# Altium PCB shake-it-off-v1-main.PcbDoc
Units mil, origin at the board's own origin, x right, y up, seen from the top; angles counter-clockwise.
Board outline 3355 x 2200 mil, 2 copper layers (Top Layer, Bottom Layer); 28 components, 43 nets, 116 pads, 6 vias.
Unrouted connection lines stored in the file: 1.
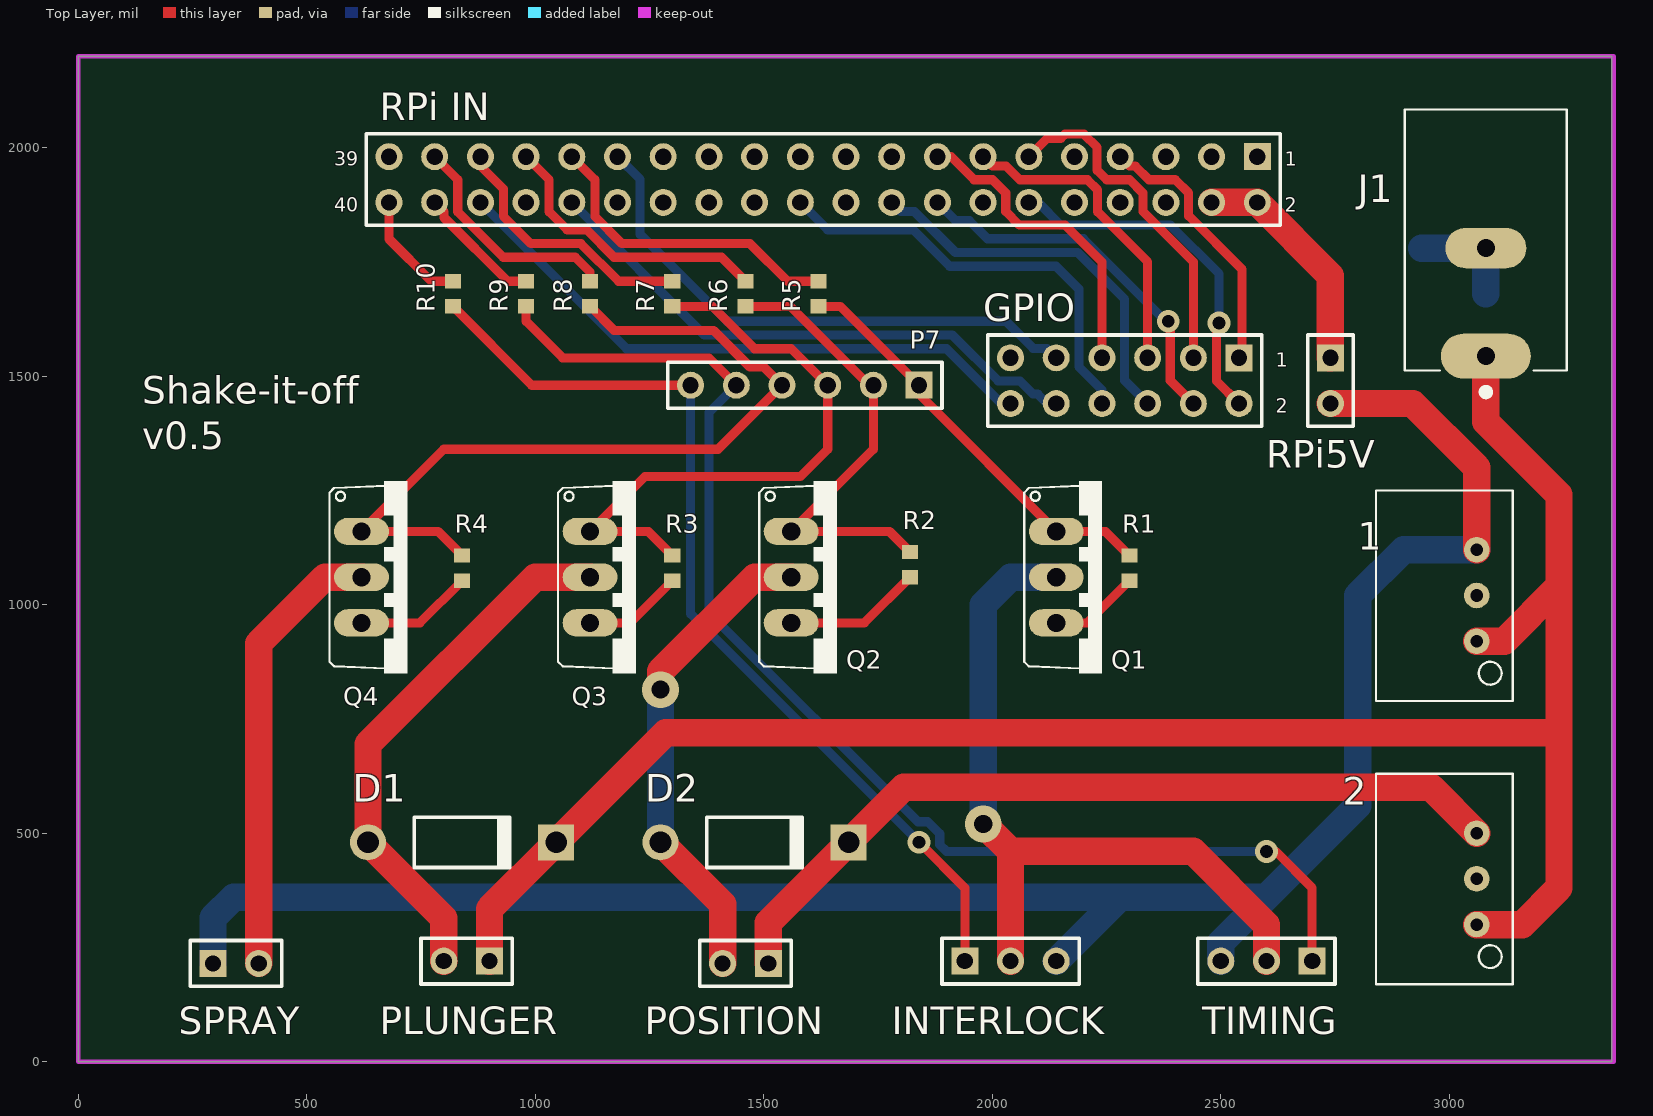
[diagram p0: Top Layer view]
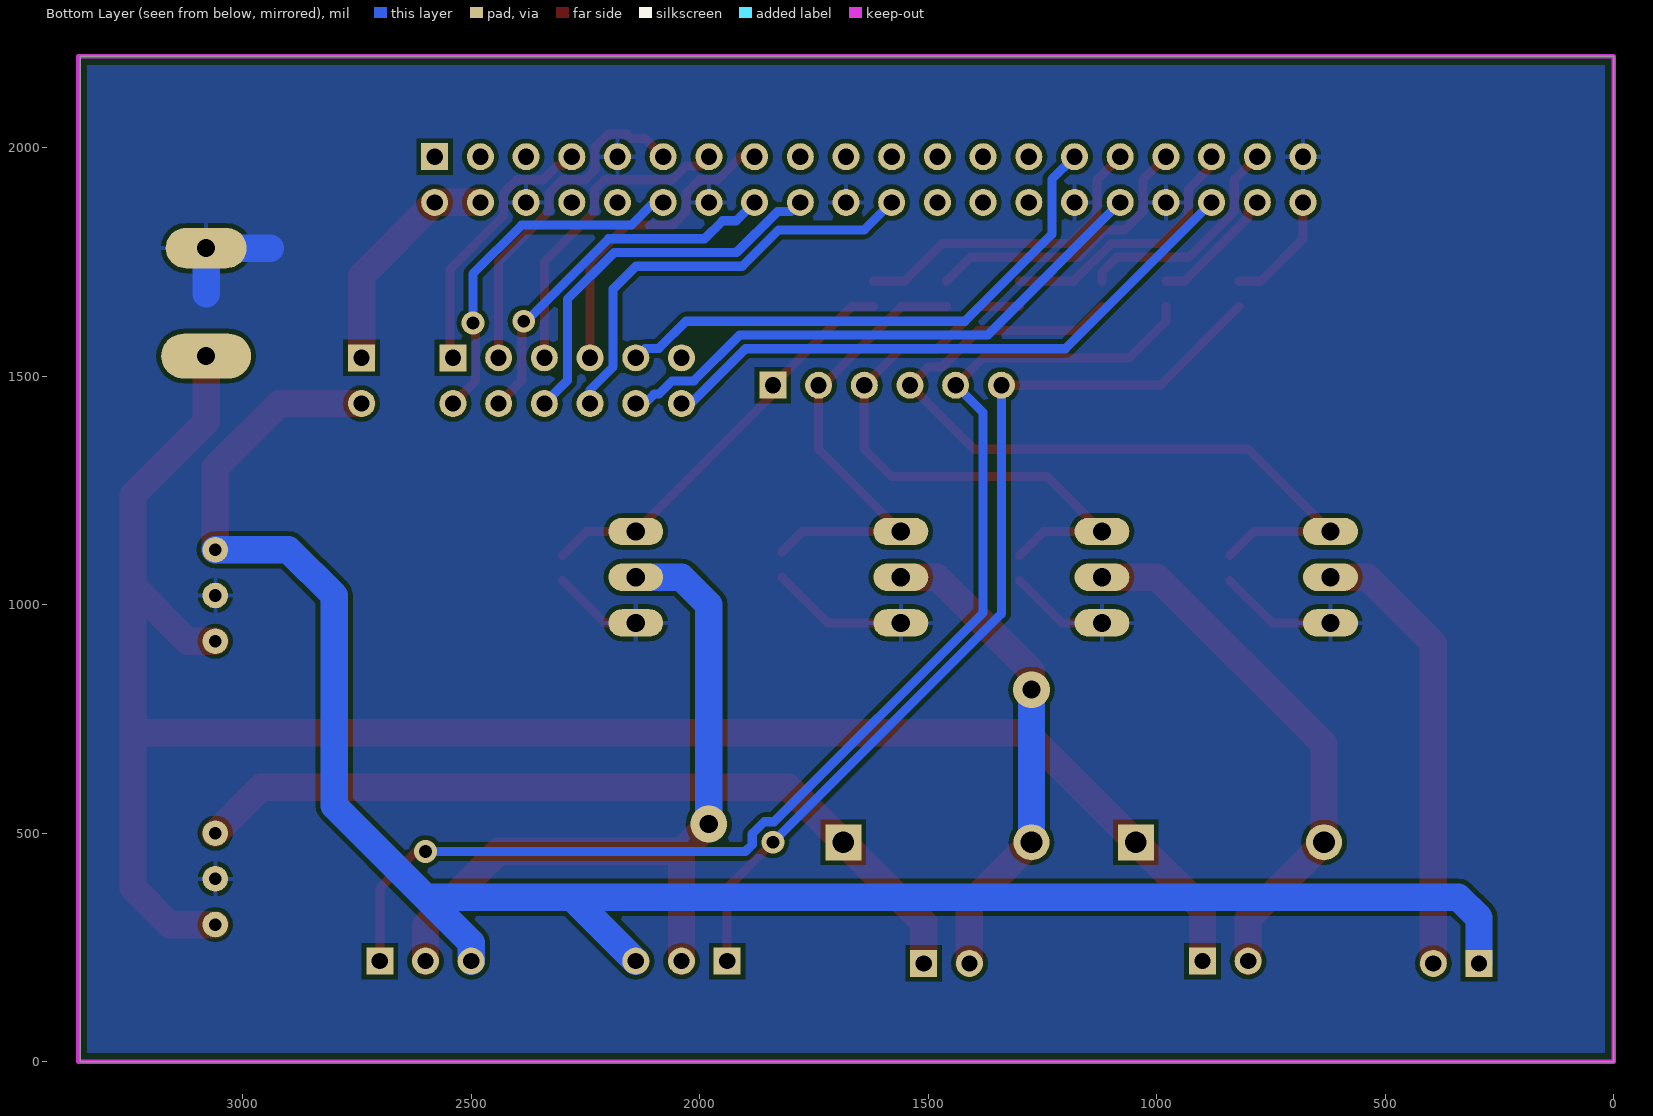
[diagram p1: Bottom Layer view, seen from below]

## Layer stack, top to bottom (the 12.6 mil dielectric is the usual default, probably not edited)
Top Solder: solder mask 0.4, Solder Resist, Dk 3.5
Top Layer: signal copper 1.4
Dielectric 1: dielectric 12.6, FR-4, Dk 4.8
Bottom Layer: signal copper 1.4
Bottom Solder: solder mask 0.4, Solder Resist, Dk 3.5

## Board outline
0,0 3355,0 3355,2200 0,2200

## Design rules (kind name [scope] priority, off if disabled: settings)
Clearance [All] p1: gap=10 ignorepadtopadclearanceinfootprint=FALSE except(0: Arc-Hole Track-Hole SMDPad-Hole THPad-Hole Via-Hole Fill-Hole Poly-Hole Region-Hole Text-Hole)
PolygonConnect [All] p1: connectstyle=Relief reliefconductorwidth=10 reliefentries=4 polygonreliefangle="90 Angle" airgapwidth=10
RoutingVias [All] p1: holewidth=35 width=60 viastyle="Through Hole" minholewidth=28 minwidth=50 maxholewidth=40 maxwidth=80
SolderMaskExpansion [All] p1: expansion=4
Width [All] p1: maxlimit=60 minlimit=20 preferedwidth=25 minimp=50.000000 maximp=50.000000 favimp=50.000000
30 further rules are at their usual default settings.

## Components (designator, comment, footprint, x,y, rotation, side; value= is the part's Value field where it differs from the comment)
1 "TSR1-2450" *TSR1-2450 3139.53,799.92 r90 top
2 "TSR1-24120" *TSR1-2450 3139.53,179.92 r90 top
D1 "Diode 1N4001" DO-41 840,480 r0 top
D2 "Diode 1N4001" DO-41 1480,480 r0 top
GPIO "Header 6X2" HDR2X6 2540,1540 r180 top (schematic designator P8)
INTERLOCK "Obstruction Sensor" HDR1X3 1940,220 r0 top (schematic designator P5)
J1 "PJ-037AH" *CUI_PJ-037AH 3080,1543.78 r90 top
P7 "Header 6" HDR1X6 1840,1480 r180 top
PLUNGER "Plunger Solenoid" HDR1X2 1510,215 r180 top (schematic designator P2)
POSITION "Piezo Solenoid" HDR1X2 900,220 r180 top (schematic designator P1)
Q1 "FQP30N06L" *TO220V 2240,1060 r270 top
Q2 "FQP30N06L" *TO220V 1660,1060 r270 top
Q3 "FQP30N06L" *TO220V 1220,1060 r270 top
Q4 "FQP30N06L" *TO220V 720,1060 r270 top
R1 "Res1" 1608[0603] 2300,1080 r90 top value=10K
R2 "Res1" 1608[0603] 1820,1087.56 r90 top value=10K
R3 "Res1" 1608[0603] 1300,1080 r90 top value=10K
R4 "Res1" 1608[0603] 840,1080 r90 top value=10K
R5 "Res1" 1608[0603] 1620,1680 r270 top value=0
R6 "Res1" 1608[0603] 1460,1680 r270 top value=0
R7 "Res1" 1608[0603] 1300,1680 r270 top value=0
R8 "Res1" 1608[0603] 1120,1680 r270 top value=0
R9 "Res1" 1608[0603] 980,1680 r270 top value=0
R10 "Res1" 1608[0603] 820,1680 r270 top value=0
RPi5V "Jumper - Remove if Powering RPi with its supply" HDR1X2 2740,1540 r270 top (schematic designator W1)
"RPi IN" "RPi GPIO In" HDR2X20 2580,1980 r180 top (schematic designator P6)
SPRAY "Sprayer" HDR1X2 295,215 r0 top (schematic designator P3)
TIMING "Safety Interlock" HDR1X3 2700,220 r180 top (schematic designator P4)

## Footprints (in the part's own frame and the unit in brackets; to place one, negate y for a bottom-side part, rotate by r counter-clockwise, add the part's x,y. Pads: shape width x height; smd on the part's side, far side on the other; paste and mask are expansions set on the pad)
1608[0603] [mm] "Chip Capacitor, Body 1.6x0.8mm, IPC High Density"
  rect 0.8x0.9 smd: 1(-0.7,0) 2(0.7,0)
  body extent -0.87,-0.48 0.87,0.48, height 1.3
*CUI_PJ-037AH [mm]
  oval 2.5x5 hole 1: 1(0,0)
  oval 2.25x4.5 hole 1: 2(6,0)
  silkscreen extent -2.2,-4.5 13.7,4.5
*TO220V [mil]
  oval 60x120 hole 40: 1(-100,-100) 2(0,-100) 3(100,-100)
  silkscreen extent -210,-170 210,0
*TSR1-2450 [mm]
  round 1.422 hole 0.7: 1(3.05,2.02) 2(5.59,2.02) 3(8.13,2.02)
  silkscreen extent -0.27,0.02 11.43,7.62
DO-41 [mm] "Diode, Axial; Body 5.2 x 2.7 mm (LxDia. max), Lead Dia. 0.86 mm (max)"
  round 2 hole 1.2: 1(-5.23,0)
  rect 2x2 hole 1.2: 2(5.23,0)
  silkscreen extent -2.65,-1.4 2.75,1.4
HDR1X2 [mm] "Connector; Header; 2 Position"
  rect 1.5x1.5 hole 0.9: 1(0,0)
  round 1.5 hole 0.9: 2(2.54,0)
  silkscreen extent -1.27,-1.27 3.81,1.27
HDR1X3 [mm] "Connector; Header; 3 Position"
  rect 1.5x1.5 hole 0.9: 1(0,0)
  round 1.5 hole 0.9: 2(2.54,0) 3(5.08,0)
  silkscreen extent -1.27,-1.27 6.35,1.27
HDR1X6 [mm] "Connector; Header; 6 Position"
  rect 1.5x1.5 hole 0.9: 1(0,0)
  round 1.5 hole 0.9: 2(2.54,0) 3(5.08,0) 4(7.62,0) 5(10.16,0) 6(12.7,0)
  silkscreen extent -1.27,-1.27 13.97,1.27
HDR2X6 [mm] "Connector; Header; 6x2 Position"
  rect 1.5x1.5 hole 0.9: 1(0,0)
  round 1.5 hole 0.9: 2(0,2.54) 3(2.54,0) 4(2.54,2.54) 5(5.08,0) 6(5.08,2.54) 7(7.62,0) 8(7.62,2.54) 9(10.16,0) 10(10.16,2.54) 11(12.7,0) 12(12.7,2.54)
  silkscreen extent -1.27,-1.27 13.97,3.81
HDR2X20 [mm] "Connector; Header; 20x2 Position"
  rect 1.5x1.5 hole 0.9: 1(0,0)
  round 1.5 hole 0.9: 2(0,2.54) 3(2.54,0) 4(2.54,2.54) 5(5.08,0) 6(5.08,2.54) 7(7.62,0) 8(7.62,2.54) 9(10.16,0) 10(10.16,2.54) 11(12.7,0) 12(12.7,2.54) 13(15.24,0) 14(15.24,2.54) 15(17.78,0) 16(17.78,2.54) 17(20.32,0) 18(20.32,2.54) 19(22.86,0) 20(22.86,2.54) 21(25.4,0) 22(25.4,2.54) 23(27.94,0) 24(27.94,2.54) 25(30.48,0) 26(30.48,2.54) 27(33.02,0) 28(33.02,2.54) 29(35.56,0) 30(35.56,2.54) 31(38.1,0) 32(38.1,2.54) 33(40.64,0) 34(40.64,2.54) 35(43.18,0) 36(43.18,2.54) 37(45.72,0) 38(45.72,2.54) 39(48.26,0) 40(48.26,2.54)
  silkscreen extent -1.27,-1.27 49.53,3.81

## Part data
1: "Converter: DC/DC; Uin: 6.5÷36V; 5VDC; Iout: 1A; SIP3; Eff", Package="SIP-3 Tracopower"
2: library part TSR1-2450, "Converter: DC/DC; Uin: 6.5÷36V; 5VDC; Iout: 1A; SIP3; Eff", Package="SIP-3 Tracopower"
D1 D2: "1 Amp General Purpose Rectifier"
GPIO: "Header, 6-Pin, Dual row"
INTERLOCK TIMING: library part "Header 3", "Header, 3-Pin"
J1: "2.0 mm Center Pin, 5.0 A, Right Angle, Through Hole, Dc Power Jack Connector", Package=None
P7: "Header, 6-Pin"
PLUNGER POSITION SPRAY: library part "Header 2", "Header, 2-Pin"
Q1 Q2 Q3 Q4: "MOSFET Transistor, N Channel, 32 A, 60 V, 27 mohm, 10 V, 2.5 V", Package="TO-220 ON Semiconductor"
R1 R2 R3 R4 R5 R6 R7 R8 R9 R10: "Resistor"
RPi5V: library part Jumper, "Jumper Wire"
"RPi IN": library part "Header 20X2", "Header, 20-Pin, Dual row"

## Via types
v1: diameter 50, hole 28, Top Layer to Bottom Layer, 4 vias
v2: diameter 80, hole 40, Top Layer to Bottom Layer, 2 vias

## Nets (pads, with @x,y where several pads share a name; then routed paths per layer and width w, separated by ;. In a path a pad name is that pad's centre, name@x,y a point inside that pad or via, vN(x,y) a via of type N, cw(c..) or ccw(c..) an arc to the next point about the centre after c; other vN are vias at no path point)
+5V: 1.3 INTERLOCK.3 RPi5V.2 SPRAY.1 TIMING.3 | length 4405.3
  Top Layer w60: RPi5V.2 2920,1440 3060,1300 1.3
  Bottom Layer w60: SPRAY.1 295,315 340,360 2280,360 ; INTERLOCK.3 2280,360 ; TIMING.3 2500,260 2600,360 ; 1.3 2900,1120 2800,1020 2800,560 2600,360 ; 2280,360 2600,360
+12V: 2.3 D2.2 PLUNGER.1 | length 1803.1
  Top Layer w60: PLUNGER.1 1510,304.09 D2.2 1805.91,600 2960,600 2.3
+24V: 1.1 2.1 D1.2 J1.1 POSITION.1 | length 4286.8
  Top Layer w60: POSITION.1 900,334.09 D1.2 1285.91,720 3240,720 ; 2.1 3160,300 3240,380 3240,720 ; 1.1 3120,920 3240,1040 ; J1.1 3080,1400 3240,1240 3240,1040 ; 3240,720 3240,1040
GND: 1.2 2.2 "RPi IN.6" "RPi IN.9" "RPi IN.14" "RPi IN.20" "RPi IN.30" "RPi IN.34" "RPi IN.39" GPIO.11 J1.2 Q1.3 Q2.3 Q3.3 Q4.3 R1.1 R2.1 R3.1 R4.1 | length 1226.5
  Top Layer w20: Q4.3 747.56,960 R4.1 ; Q3.3 1207.56,960 R3.1 ; Q2.3 1720,960 R2.1 ; Q1.3 2207.56,960 R1.1
  Bottom Layer w20: 3060,1700 3060,1710.24
  Bottom Layer w60: 2940,1780 J1.2 3080,1680
GPIO4: "RPi IN.7" GPIO.1 | length 594
  Top Layer w20: 2280,1980 2300.47,1959.53 2312.94,1959.53 2342.94,1929.53 2400.51,1929.53 2429.53,1900.51 2429.53,1850.47 2546.33,1733.67 2546.33,1546.33 GPIO.1
GPIO5: "RPi IN.29" GPIO.9 | length 1212.5
  Bottom Layer w20: 1180,1980 1229.53,1930.47 1229.53,1810.47 1420,1620 2030.04,1620 2089.53,1560.51 2119.49,1560.51 GPIO.9
GPIO6: "RPi IN.31" R5.1 | length 699.7
  Top Layer w20: 1080,1980 1130.47,1929.53 1130.47,1849.53 1190,1790 1470,1790 1552.44,1707.56 R5.1
GPIO12: "RPi IN.32" GPIO.10 | length 1242.3
  Bottom Layer w20: 1080,1880 1370,1590 1912.43,1590 2012.9,1489.53 2060.51,1489.53 2089.53,1460.51 2099.49,1460.51 2120,1440 GPIO.10
GPIO13: "RPi IN.33" R6.1 | length 633.9
  Top Layer w20: 980,1980 1030.47,1929.53 1030.47,1859.49 1069.96,1820 1112.41,1820 1172.41,1760 1407.56,1760 R6.1
GPIO16: "RPi IN.36" GPIO.12 | length 1342.3
  Bottom Layer w20: 880,1880 1200,1560 1900,1560 2020,1440 GPIO.12
GPIO17: "RPi IN.11" GPIO.3 | length 759.1
  Top Layer w20: 2080,1980 2120,2020 2149.96,2020 2159.49,2029.53 2200.51,2029.53 2229.53,2000.51 2229.53,1950.47 2250.47,1929.53 2300.51,1929.53 2329.53,1900.51 2329.53,1860.43 2440,1749.96 GPIO.3
GPIO18: "RPi IN.12" GPIO.2 | length 787.7
  Top Layer w20: v1(2496.33,1616.33) 2490.47,1610.47 2490.47,1489.53 GPIO.2
  Bottom Layer w20: 2080,1880 2100,1880 2149.53,1830.47 2389.53,1830.47 2496.33,1723.67 v1(2496.33,1616.33)
GPIO19: "RPi IN.35" R7.1 | length 579.5
  Top Layer w20: 880,1980 880,1960 930.47,1909.53 930.47,1849.96 990.43,1790 1099.99,1790 1182.43,1707.56 R7.1
GPIO20: "RPi IN.38" R9.1 | length 278.7
  Top Layer w20: 780,1880 800.47,1859.53 800.47,1847.06 939.97,1707.56 R9.1
GPIO21: "RPi IN.40" R10.1 | length 258.3
  Top Layer w20: 680,1880 680,1800 772.44,1707.56 R10.1
GPIO22: "RPi IN.15" GPIO.7 | length 688.7
  Top Layer w20: 1880,1980 1909.96,1980 1960.43,1929.53 2000.51,1929.53 2029.53,1900.51 2029.53,1860.43 2059.49,1830.47 2159.49,1830.47 2240,1749.96 GPIO.7
GPIO23: "RPi IN.16" GPIO.4 | length 815.5
  Top Layer w20: v1(2385,1620) 2389.53,1615.47 2389.53,1490.47 GPIO.4
  Bottom Layer w20: 1880,1880 1920,1840 1949.96,1840 1989.49,1800.47 2199.53,1800.47 2380,1620 v1(2385,1620)
GPIO24: "RPi IN.18" GPIO.6 | length 846.3
  Bottom Layer w20: 1780,1880 1800,1860 1829.96,1860 1919.49,1770.47 2187.1,1770.47 2289.53,1668.05 2289.53,1490.47 GPIO.6
GPIO25: "RPi IN.22" GPIO.8 | length 959.4
  Bottom Layer w20: 1580,1880 1640,1820 1827.53,1820 1907.06,1740.47 2139.53,1740.47 2189.53,1690.47 2189.53,1520.43 2240,1469.96 GPIO.8
GPIO26: "RPi IN.37" R8.1 | length 505.6
  Top Layer w20: 780,1980 830.47,1929.53 830.47,1859.49 929.96,1760 1087.56,1760 1120,1727.56 R8.1
GPIO27: "RPi IN.13" GPIO.5 | length 693.1
  Top Layer w20: 1980,1980 2000.47,1959.53 2030.43,1959.53 2060.43,1929.53 2208.05,1929.53 2230.47,1907.1 2230.47,1859.49 2340,1749.96 GPIO.5
ID_SC: "RPi IN.28"
ID_SDA: "RPi IN.27"
INTRLCK_SIG: P7.5 R9.2 TIMING.1 | length 2816.2
  Top Layer w20: R9.2 980,1620 1060,1540 1380,1540 P7.5 ; v1(2600,460) 2620,460 2700,380 TIMING.1
  Bottom Layer w20: P7.5 1380,1420 1380,982.43 1837.43,525 1858.64,525 1885,498.64 1885,475 1900,460 v1(2600,460)
MISO: "RPi IN.21"
MOSI: "RPi IN.19"
NetP6_2: "RPi IN.2" "RPi IN.4" RPi5V.1 | length 506.3
  Top Layer w60: 2480,1880 2580,1880 2740,1720 RPi5V.1
OBSTR_SIG: INTERLOCK.1 P7.6 R10.2 | length 2100
  Top Layer w20: R10.2 992.44,1480 P7.6 ; v1(1840,480) 1940,380 INTERLOCK.1
  Bottom Layer w20: P7.6 1340,980 v1(1840,480)
PIEZO-: D1.1 POSITION.2 Q3.2 | length 1180.3
  Top Layer w60: POSITION.2 800,314.09 D1.1 634.09,694.09 1000,1060 Q3.2
PIEZO_CTRL: P7.3 Q3.1 R3.2 R7.2 | length 1347.7
  Top Layer w20: R3.2 1247.56,1160 Q3.1 1240,1280 1580,1280 1640,1340 P7.3 1560,1560 1480,1560 1387.56,1652.44 R7.2
PLUNG-: D2.1 PLUNGER.2 Q2.2 | length 1066.6
  Top Layer w60: D2.1 1410,344.09 PLUNGER.2 ; v2(1274.09,814.09) 1274.09,854.09 1480,1060 Q2.2
  Bottom Layer w60: D2.1 v2(1274.09,814.09)
PLUNG_CTRL: P7.2 Q2.1 R2.2 R6.2 | length 1024.6
  Top Layer w20: R6.2 1558.25,1652.44 1730.69,1480 P7.2 1740,1340 Q2.1 1775.12,1160 R2.2
RXD0: "RPi IN.10"
SCL: "RPi IN.5"
SCLK: "RPi IN.23"
SDA: "RPi IN.3"
SENS-: INTERLOCK.2 Q1.2 TIMING.2 | length 1696
  Top Layer w60: v2(1980,520) 2040,460 ; INTERLOCK.2 2040,460 ; TIMING.2 2600,300 2440,460 2040,460
  Bottom Layer w60: v2(1980,520) 1980,1000 2040,1060 Q1.2
SENS_CTRL: P7.1 Q1.1 R1.2 R5.2 | length 917.4
  Top Layer w20: R5.2 1667.56,1652.44 P7.1 1840,1460 Q1.1 2247.56,1160 R1.2
SPICE0: "RPi IN.24"
SPICE1: "RPi IN.26"
SPRAY-: Q4.2 SPRAY.2 | length 985.1
  Top Layer w60: SPRAY.2 395,915 540,1060 Q4.2
SPRAY_CTRL: P7.4 Q4.1 R4.2 R8.2 | length 1785.7
  Top Layer w20: R4.2 787.56,1160 Q4.1 800,1340 1400,1340 P7.4 1500,1520 1470.04,1520 1390.04,1600 1172.44,1600 R8.2
TXD0: "RPi IN.8"
pads on no net: "RPi IN.1" "RPi IN.17" "RPi IN.25"

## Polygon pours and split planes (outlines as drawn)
GND on Bottom Layer "Bottom Layer-GND" (solid, remove dead copper, pour order 0): 20,2180 3340,2180 3340,20 20,20

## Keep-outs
Keep-Out Layer:
  lines w10: 0,0 3360,0 3360,2200 0,2200 0,0

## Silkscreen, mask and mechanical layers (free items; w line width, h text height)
Top Overlay:
  text "Shake-it-off" at 140,1440 h60
  text "v0.5" at 140,1340 h60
